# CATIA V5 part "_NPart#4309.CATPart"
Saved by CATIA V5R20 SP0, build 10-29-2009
Part number: 1BOLAØ2,3
Revision: ANY
Definition: UNKNOWN
Nomenclature: 1BOLAØ2,3
Source: Unknown
Bounding box of the stored display mesh (mm): x -1.19 to 1.19, y -1.19 to 1.19, z -1.19 to 1.19
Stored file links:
  C:\Users\Utente\Desktop\IO LAVORO\3D X SITO CF\CUMSA\3D files AE\AE 041620\_NPart#4309.CATPart
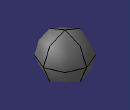
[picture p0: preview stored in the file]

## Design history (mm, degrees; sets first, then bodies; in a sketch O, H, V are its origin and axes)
Body1 "Revolución1" (main body)
  Solid1: solid without history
